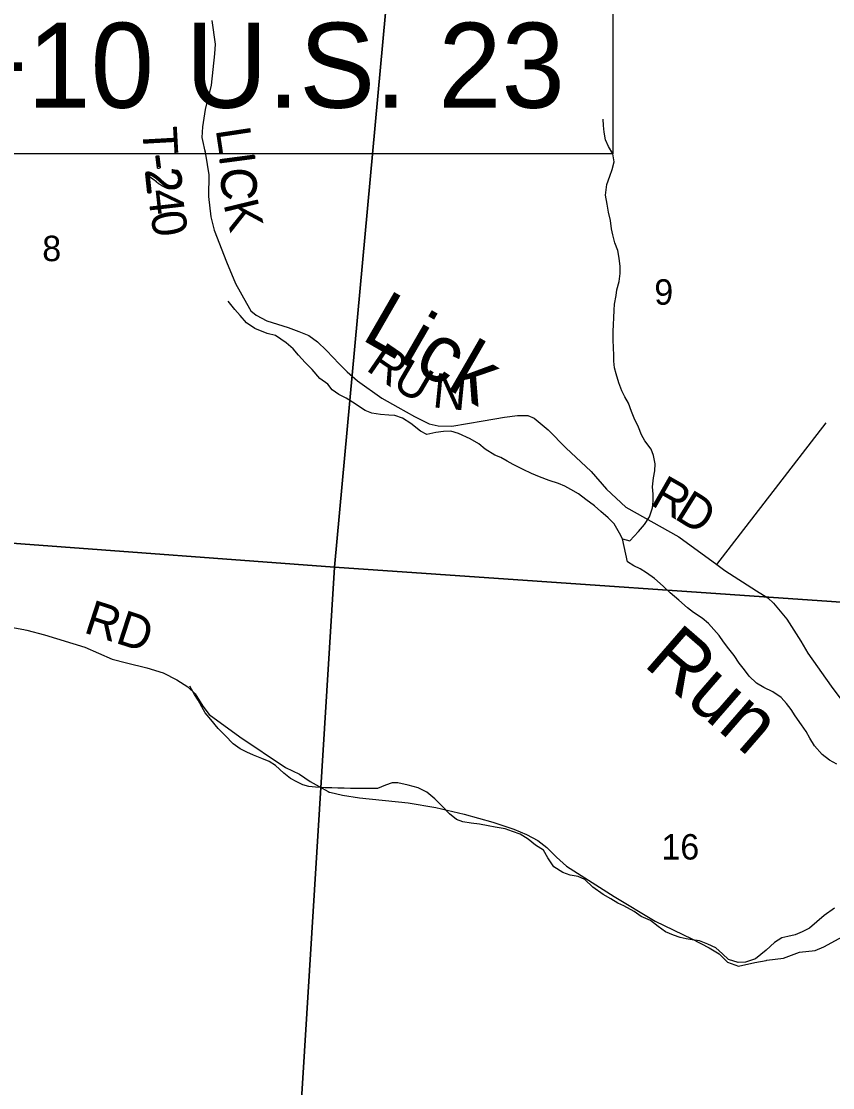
# Model space of a CAD drawing. Extents: x 0 to 34, y 0 to 22.
# Drawn here: x 6.981 to 8.316, y 15.475 to 17.231 of the extents above; entities that cross this region are included whole.
import ezdxf

# ---------------------------------------------------------------- set-up
doc = ezdxf.new("R2010")
doc.units = 0
for name, color, linetype in [('GM_X_Corporation', 7, 'Continuous'), ('GM_X_Minor_River', 7, 'Continuous'), ('GM_X_Minor_River_Text', 7, 'Continuous'), ('GM_X_Section_Text', 7, 'Continuous'), ('GM_X_Township_Road', 7, 'Continuous'), ('GM_X_Township_Road_Text', 7, 'Continuous'), ('SH_Data', 7, 'Continuous'), ('SH_Text', 7, 'Continuous')]:
    doc.layers.add(name, color=color, linetype=linetype)

msp = doc.modelspace()

# ---------------------------------------------------------------- linework, layer by layer
at = {"layer": 'GM_X_Corporation'}
for points in [[(6.5737, 17.4057), (7.5885, 17.3345), (7.4964, 16.3324), (6.463, 16.4089)], [(7.5885, 17.3345), (8.5882, 17.2585), (8.4813, 16.2644), (7.4964, 16.3324)], [(6.463, 16.4089), (7.4964, 16.3324), (7.434, 15.3319), (6.4021, 15.41)], [(7.4964, 16.3324), (8.4813, 16.2644), (8.4262, 15.2749), (7.434, 15.3319)]]:
    msp.add_lwpolyline(points, close=True, dxfattribs=at)
at = {"layer": 'GM_X_Minor_River'}
for p, q in [((7.9543, 17.0126), (7.9514, 17.0176)), ((7.9565, 16.9993), (7.9543, 17.0126)), ((7.9534, 16.9868), (7.9565, 16.9993)), ((7.9446, 16.9622), (7.9492, 16.9758)), ((7.9492, 16.9758), (7.9534, 16.9868)), ((7.9422, 16.9444), (7.9446, 16.9622)), ((7.9448, 16.9296), (7.9422, 16.9444))]:
    msp.add_line(p, q, dxfattribs=at)
for points in [[(7.9701, 16.3786), (7.9822, 16.3755), (7.9967, 16.391), (8.0066, 16.4023), (8.015, 16.4148), (8.0196, 16.43), (8.0208, 16.441), (8.0209, 16.4524), (8.0198, 16.4645), (8.0214, 16.4793), (8.0237, 16.491), (8.0241, 16.5024), (8.0215, 16.5161), (8.0174, 16.5267), (8.0069, 16.54), (8.0016, 16.5499), (7.9968, 16.5629), (7.9896, 16.5777), (7.9852, 16.5883), (7.9799, 16.602), (7.9743, 16.6126), (7.9694, 16.6225), (7.9642, 16.6354), (7.9597, 16.6506), (7.9571, 16.6605), (7.956, 16.6711), (7.9561, 16.6825), (7.9557, 16.6924), (7.9551, 16.7076), (7.9547, 16.7201), (7.9555, 16.7319), (7.956, 16.7425), (7.9564, 16.755), (7.9572, 16.7649), (7.9596, 16.7793), (7.9611, 16.7887), (7.9646, 16.8024), (7.9666, 16.8157), (7.9662, 16.8274), (7.9648, 16.8407), (7.9626, 16.8532), (7.9577, 16.8662), (7.9544, 16.8791), (7.9521, 16.8889), (7.9503, 16.903), (7.9474, 16.9163), (7.9448, 16.9296), (7.9422, 16.9444), (7.9446, 16.9622), (7.9492, 16.9758), (7.9534, 16.9868), (7.9565, 16.9993), (7.9543, 17.0126), (7.9475, 17.0244), (7.9423, 17.0358), (7.94, 17.048), (7.939, 17.059), (7.9386, 17.0696)], [(7.7904, 16.5014), (7.7806, 16.5067), (7.77, 16.5128), (7.7602, 16.5167), (7.7443, 16.5266), (7.7338, 16.535), (7.7194, 16.5434), (7.7001, 16.5522), (7.6876, 16.556), (7.6755, 16.5553), (7.663, 16.5538), (7.6482, 16.5508), (7.638, 16.5562), (7.6218, 16.5688), (7.6082, 16.5775), (7.5957, 16.5818), (7.5859, 16.5826), (7.5719, 16.5834), (7.5579, 16.5857), (7.5469, 16.5903), (7.5258, 16.6036), (7.5152, 16.6105), (7.5031, 16.6166), (7.4925, 16.6239), (7.485, 16.6334), (7.4722, 16.6429), (7.4593, 16.6574), (7.448, 16.6692), (7.4371, 16.6814), (7.4281, 16.6916), (7.4164, 16.7016), (7.399, 16.7134), (7.3854, 16.7168), (7.365, 16.7253), (7.3514, 16.7344), (7.3408, 16.7462), (7.3322, 16.7565), (7.3212, 16.7698)], [(8.3232, 16.0081), (8.3112, 16.0146), (8.2991, 16.0237), (8.2866, 16.0382), (8.2788, 16.0507), (8.2727, 16.0618), (8.2652, 16.0728), (8.2547, 16.0872), (8.2479, 16.0979), (8.2404, 16.1078), (8.2314, 16.1177), (8.2178, 16.1272), (8.203, 16.1341), (8.1909, 16.1414), (8.1789, 16.1528), (8.1713, 16.1634), (8.1623, 16.1741), (8.154, 16.1866), (8.1454, 16.1977), (8.1367, 16.2091), (8.1296, 16.2197), (8.1205, 16.2296), (8.1119, 16.2395), (8.1013, 16.2483), (8.0873, 16.2575), (8.0775, 16.2651), (8.0632, 16.278), (8.0489, 16.2899), (8.0375, 16.3009), (8.0228, 16.3135), (8.0096, 16.3226), (7.9994, 16.3295), (7.9888, 16.3345), (7.9783, 16.341), (7.9701, 16.3786), (7.9656, 16.3881), (7.9566, 16.4036), (7.9468, 16.4135), (7.9344, 16.4238), (7.9242, 16.4334), (7.9102, 16.4433), (7.8978, 16.4528), (7.8853, 16.4601), (7.8755, 16.4654), (7.8649, 16.47), (7.8494, 16.4746), (7.8335, 16.4811), (7.8203, 16.4865), (7.8067, 16.493), (7.7904, 16.5014)], [(7.2715, 16.1132), (7.2658, 16.1227), (7.2583, 16.1364)], [(8.3191, 15.7709), (8.3023, 15.7589), (8.2902, 15.7483), (8.2784, 15.7377), (8.2658, 15.7321), (8.2545, 15.7268), (8.2423, 15.7242), (8.2325, 15.7219), (8.2203, 15.7144), (8.2066, 15.7019), (8.1891, 15.6876), (8.1728, 15.6819), (8.1607, 15.6812), (8.1448, 15.6866), (8.135, 15.6957), (8.1237, 15.7053), (8.1108, 15.7118), (8.0972, 15.7168), (8.0851, 15.7187), (8.0749, 15.7202), (8.065, 15.7226), (8.0545, 15.7264), (8.0412, 15.7321), (8.0292, 15.7409), (8.0163, 15.7504), (8.0012, 15.7573), (7.9895, 15.7653), (7.9725, 15.7745), (7.9627, 15.7791), (7.951, 15.7863), (7.9385, 15.7932), (7.9215, 15.8054), (7.9083, 15.818), (7.8973, 15.823), (7.8841, 15.8249), (7.872, 15.8295), (7.8573, 15.8387), (7.8475, 15.8535), (7.8404, 15.8664), (7.8268, 15.8748), (7.8151, 15.8844), (7.8019, 15.8924), (7.7894, 15.8973), (7.7773, 15.9012), (7.7606, 15.9043), (7.7489, 15.9062), (7.7349, 15.9089), (7.7213, 15.9109), (7.7073, 15.9128), (7.697, 15.9167), (7.6857, 15.9262), (7.6729, 15.9395), (7.6612, 15.9509), (7.6484, 15.9616), (7.634, 15.9689), (7.6174, 15.9735), (7.6007, 15.9773), (7.5909, 15.9774), (7.5803, 15.9732), (7.567, 15.968), (7.5575, 15.9676), (7.5461, 15.9677), (7.5325, 15.9677), (7.5227, 15.9681), (7.5121, 15.9685), (7.5015, 15.9686), (7.4916, 15.969), (7.481, 15.969), (7.4651, 15.9702), (7.4541, 15.9714), (7.4439, 15.9741), (7.4341, 15.9787), (7.4239, 15.9844), (7.4129, 15.9932), (7.399, 16.0058), (7.3888, 16.0122), (7.3767, 16.0172), (7.3627, 16.0226), (7.3517, 16.0276), (7.3408, 16.0333), (7.3294, 16.0413), (7.3163, 16.055), (7.3046, 16.0664), (7.2925, 16.0813), (7.2831, 16.0923), (7.2778, 16.1022), (7.2715, 16.1132)]]:
    msp.add_lwpolyline(points, dxfattribs=at)
at = {"layer": 'GM_X_Township_Road'}
for p, q in [((7.2826, 17.0185), (7.284, 17.0121)), ((7.284, 17.0121), (7.2892, 16.9783)), ((7.2892, 16.9783), (7.2887, 16.9425)), ((8.1257, 16.3365), (8.3057, 16.5696))]:
    msp.add_line(p, q, dxfattribs=at)
for points in [[(7.2945, 17.2323), (7.2997, 17.1932), (7.2989, 17.1772), (7.2931, 17.1256), (7.2835, 17.0854), (7.2788, 17.0569), (7.278, 17.0394), (7.284, 17.0121), (7.2892, 16.9783), (7.2887, 16.9425), (7.2928, 16.9091), (7.298, 16.8871), (7.3184, 16.8346), (7.3334, 16.7993), (7.3515, 16.7665), (7.3583, 16.7544), (7.367, 16.7471), (7.3848, 16.7376), (7.42, 16.7269), (7.4374, 16.72), (7.4541, 16.7135), (7.4681, 16.7032), (7.4828, 16.6887), (7.504, 16.667), (7.5168, 16.6537), (7.5338, 16.6388), (7.5743, 16.6106), (7.6004, 16.5954), (7.628, 16.5801), (7.6519, 16.5679), (7.667, 16.5648), (7.6894, 16.5644), (7.7409, 16.5729), (7.7762, 16.5793), (7.7974, 16.5819), (7.8145, 16.5819), (7.8247, 16.5773), (7.8478, 16.5582), (7.8773, 16.5281), (7.9015, 16.5055), (7.9185, 16.4897), (7.9441, 16.4604), (7.9759, 16.431), (8.0629, 16.3822), (8.1257, 16.3365), (8.1389, 16.3269), (8.1911, 16.293), (8.2093, 16.2815), (8.2187, 16.2731), (8.2406, 16.2465), (8.264, 16.2103), (8.2753, 16.1906), (8.3138, 16.1365), (8.369, 16.0623)], [(6.9268, 16.2398), (6.9849, 16.2293)], [(6.9849, 16.2293), (6.9868, 16.229), (6.9897, 16.2284), (7.0188, 16.2209), (7.0854, 16.2004), (7.1299, 16.1805), (7.1537, 16.1745), (7.1874, 16.1662), (7.2142, 16.1583), (7.2369, 16.1466), (7.2545, 16.135), (7.2669, 16.1235), (7.2796, 16.1036), (7.2896, 16.0899), (7.3404, 16.0528), (7.4153, 16.0026), (7.4383, 15.9917), (7.456, 15.9794), (7.4858, 15.963)], [(7.4858, 15.963), (7.4875, 15.962), (7.4884, 15.9616), (7.5096, 15.9568), (7.5372, 15.9526), (7.6176, 15.9441), (7.663, 15.9368), (7.7099, 15.9256), (7.7568, 15.9125), (7.7916, 15.9008), (7.812, 15.8922), (7.8308, 15.8821), (7.8459, 15.8709), (7.8616, 15.8548), (7.8781, 15.8402), (7.9568, 15.7899), (8.0242, 15.7497), (8.0842, 15.7201), (8.1132, 15.7057), (8.1294, 15.6957), (8.1429, 15.6819), (8.1614, 15.6756), (8.1884, 15.6813), (8.2067, 15.6849), (8.2077, 15.685)], [(8.2077, 15.685), (8.2352, 15.6888), (8.2619, 15.6983), (8.2877, 15.7014), (8.3018, 15.7073), (8.3332, 15.7244), (8.3511, 15.7333), (8.4189, 15.7512), (8.4387, 15.754), (8.4504, 15.7542)]]:
    msp.add_lwpolyline(points, dxfattribs=at)
at = {"layer": 'GM_X_Township_Road_Text'}
for p, q in [((7.3088, 17.0029), (7.3631, 17.0101)), ((7.2047, 16.9897), (7.2028, 17.0079)), ((7.2072, 17.0084), (7.2091, 16.9901)), ((7.3638, 17.0048), (7.3095, 16.9976)), ((7.1891, 16.9492), (7.1858, 16.9795)), ((7.1913, 16.9809), (7.2048, 16.9707)), ((7.2071, 16.9887), (7.2071, 16.9887)), ((7.1917, 16.9478), (7.1917, 16.9478)), ((7.319, 16.9443), (7.319, 16.9443))]:
    msp.add_line(p, q, dxfattribs=at)
msp.add_lwpolyline([(7.2029, 16.9663), (7.191, 16.9754), (7.1938, 16.9497)], dxfattribs=at)
for points in [[(7.3631, 17.0101), (7.3634, 17.0101), (7.3636, 17.01)], [(7.3636, 17.01), (7.3639, 17.0098), (7.364, 17.0095)], [(7.2028, 17.0079), (7.2027, 17.0085), (7.2032, 17.0089)], [(7.2032, 17.0089), (7.2036, 17.0093), (7.2048, 17.0094)], [(7.2048, 17.0094), (7.2061, 17.0096), (7.2066, 17.0093)], [(7.2066, 17.0093), (7.2071, 17.0089), (7.2072, 17.0084)], [(7.3079, 17.0013), (7.308, 17.0019), (7.308, 17.0022)], [(7.308, 17.0001), (7.3079, 17.0008), (7.3079, 17.0013)], [(7.308, 17.0022), (7.3081, 17.0025), (7.3083, 17.0027)], [(7.3083, 16.9988), (7.3081, 16.9993), (7.308, 17.0001)], [(7.3083, 17.0027), (7.3085, 17.0028), (7.3088, 17.0029)], [(7.3086, 16.998), (7.3084, 16.9983), (7.3083, 16.9988)], [(7.309, 16.9976), (7.3088, 16.9977), (7.3086, 16.998)], [(7.3095, 16.9976), (7.3092, 16.9975), (7.309, 16.9976)], [(7.3643, 17.005), (7.3641, 17.0048), (7.3638, 17.0048)], [(7.364, 17.0095), (7.3642, 17.0092), (7.3644, 17.0087)], [(7.3646, 17.0054), (7.3645, 17.0051), (7.3643, 17.005)], [(7.3644, 17.0087), (7.3645, 17.0083), (7.3646, 17.0076)], [(7.3646, 17.0076), (7.3647, 17.0068), (7.3647, 17.0063)], [(7.3647, 17.0063), (7.3647, 17.0058), (7.3646, 17.0054)], [(7.1858, 16.9803), (7.1859, 16.9806), (7.1862, 16.9809)], [(7.1858, 16.9795), (7.1857, 16.9799), (7.1858, 16.9803)], [(7.1862, 16.9809), (7.1864, 16.9812), (7.1869, 16.9814)], [(7.1869, 16.9814), (7.1874, 16.9816), (7.188, 16.9817)], [(7.188, 16.9817), (7.1886, 16.9817), (7.189, 16.9817)], [(7.189, 16.9817), (7.1894, 16.9817), (7.1898, 16.9816)], [(7.1898, 16.9816), (7.1902, 16.9816), (7.1905, 16.9814)], [(7.1905, 16.9814), (7.1909, 16.9812), (7.1913, 16.9809)], [(7.2053, 16.9888), (7.2048, 16.9891), (7.2047, 16.9897)], [(7.2071, 16.9887), (7.2058, 16.9885), (7.2053, 16.9888)], [(7.2081, 16.9888), (7.2077, 16.9887), (7.2071, 16.9887)], [(7.2087, 16.9892), (7.2085, 16.989), (7.2081, 16.9888)], [(7.209, 16.9896), (7.209, 16.9894), (7.2087, 16.9892)], [(7.2091, 16.9901), (7.2091, 16.9899), (7.209, 16.9896)], [(7.2332, 16.9844), (7.2332, 16.9847), (7.2333, 16.9849)], [(7.2342, 16.9829), (7.2333, 16.9839), (7.2332, 16.9844)], [(7.2333, 16.9849), (7.2334, 16.9851), (7.2337, 16.9853)], [(7.2337, 16.9853), (7.234, 16.9855), (7.2344, 16.9856)], [(7.2362, 16.9804), (7.2351, 16.9819), (7.2342, 16.9829)], [(7.2344, 16.9856), (7.2348, 16.9857), (7.2354, 16.9858)], [(7.2354, 16.9858), (7.2359, 16.9858), (7.2363, 16.9858)], [(7.2383, 16.9767), (7.2373, 16.9788), (7.2362, 16.9804)], [(7.2363, 16.9858), (7.2366, 16.9858), (7.2369, 16.9858)], [(7.2369, 16.9858), (7.2372, 16.9857), (7.2375, 16.9856)], [(7.2375, 16.9856), (7.2377, 16.9855), (7.2382, 16.985)], [(7.2382, 16.985), (7.2387, 16.9846), (7.2396, 16.9834)], [(7.2396, 16.9719), (7.2393, 16.9747), (7.2383, 16.9767)], [(7.2396, 16.9834), (7.2405, 16.9823), (7.2414, 16.9806)], [(7.2414, 16.9806), (7.2424, 16.9789), (7.2432, 16.9767)], [(7.2432, 16.9767), (7.244, 16.9745), (7.2442, 16.9722)], [(7.3117, 16.971), (7.3134, 16.9753), (7.3169, 16.9785)], [(7.3169, 16.9785), (7.3204, 16.9817), (7.3255, 16.9835)], [(7.3281, 16.9782), (7.3237, 16.9768), (7.3208, 16.9744)], [(7.3255, 16.9835), (7.3307, 16.9853), (7.3375, 16.9855)], [(7.338, 16.9798), (7.3324, 16.9796), (7.3281, 16.9782)], [(7.3375, 16.9855), (7.3444, 16.9857), (7.3499, 16.9842)], [(7.3485, 16.9788), (7.3439, 16.98), (7.338, 16.9798)], [(7.3563, 16.9753), (7.3531, 16.9776), (7.3485, 16.9788)], [(7.3499, 16.9842), (7.3555, 16.9826), (7.3594, 16.9796)], [(7.3612, 16.9698), (7.3595, 16.9731), (7.3563, 16.9753)], [(7.3594, 16.9796), (7.3633, 16.9765), (7.3655, 16.9722)], [(7.2125, 16.9597), (7.2084, 16.9621), (7.2029, 16.9663)], [(7.2048, 16.9707), (7.2097, 16.9669), (7.2136, 16.9648)], [(7.22, 16.9561), (7.2166, 16.9573), (7.2125, 16.9597)], [(7.2136, 16.9648), (7.2174, 16.9626), (7.2204, 16.9616)], [(7.2204, 16.9616), (7.2235, 16.9606), (7.2259, 16.9604)], [(7.2259, 16.9604), (7.2283, 16.9602), (7.2303, 16.9605)], [(7.2303, 16.9605), (7.2324, 16.9607), (7.2342, 16.9616)], [(7.2342, 16.9616), (7.2361, 16.9625), (7.2373, 16.9639)], [(7.2412, 16.9599), (7.2394, 16.9578), (7.2369, 16.9565)], [(7.2373, 16.9639), (7.2386, 16.9654), (7.2392, 16.9674)], [(7.2392, 16.9674), (7.2399, 16.9694), (7.2396, 16.9719)], [(7.2438, 16.9652), (7.243, 16.9621), (7.2412, 16.9599)], [(7.2442, 16.9722), (7.2447, 16.9682), (7.2438, 16.9652)], [(7.3101, 16.9612), (7.31, 16.9666), (7.3117, 16.971)], [(7.311, 16.9552), (7.3103, 16.9579), (7.3101, 16.9612)], [(7.3164, 16.9685), (7.315, 16.9651), (7.3151, 16.9608)], [(7.3151, 16.9608), (7.3152, 16.9572), (7.3162, 16.9546)], [(7.3208, 16.9744), (7.3179, 16.972), (7.3164, 16.9685)], [(7.363, 16.9625), (7.3629, 16.9665), (7.3612, 16.9698)], [(7.3623, 16.9563), (7.3631, 16.9589), (7.363, 16.9625)], [(7.3655, 16.9722), (7.3677, 16.9678), (7.3679, 16.9624)], [(7.3675, 16.9575), (7.3671, 16.9551), (7.3665, 16.9531)], [(7.3679, 16.9624), (7.3679, 16.9599), (7.3675, 16.9575)], [(7.1894, 16.9485), (7.1891, 16.9488), (7.1891, 16.9492)], [(7.1899, 16.9481), (7.1896, 16.9482), (7.1894, 16.9485)], [(7.1907, 16.9478), (7.1902, 16.9479), (7.1899, 16.9481)], [(7.1917, 16.9478), (7.1912, 16.9478), (7.1907, 16.9478)], [(7.1926, 16.948), (7.1922, 16.9479), (7.1917, 16.9478)], [(7.1933, 16.9485), (7.1931, 16.9482), (7.1926, 16.948)], [(7.1937, 16.949), (7.1936, 16.9487), (7.1933, 16.9485)], [(7.1938, 16.9497), (7.1939, 16.9493), (7.1937, 16.949)], [(7.226, 16.9548), (7.2233, 16.955), (7.22, 16.9561)], [(7.2314, 16.955), (7.2287, 16.9547), (7.226, 16.9548)], [(7.2369, 16.9565), (7.2343, 16.9553), (7.2314, 16.955)], [(7.3127, 16.9504), (7.3118, 16.9525), (7.311, 16.9552)], [(7.3147, 16.9469), (7.3137, 16.9483), (7.3127, 16.9504)], [(7.3161, 16.9452), (7.3157, 16.9456), (7.3147, 16.9469)], [(7.3168, 16.9446), (7.3166, 16.9448), (7.3161, 16.9452)], [(7.3162, 16.9546), (7.3172, 16.952), (7.3184, 16.9501)], [(7.3174, 16.9444), (7.3171, 16.9445), (7.3168, 16.9446)], [(7.3181, 16.9443), (7.3177, 16.9443), (7.3174, 16.9444)], [(7.319, 16.9443), (7.3185, 16.9442), (7.3181, 16.9443)], [(7.3184, 16.9501), (7.3195, 16.9483), (7.3205, 16.9471)], [(7.3202, 16.9444), (7.3197, 16.9443), (7.319, 16.9443)], [(7.3209, 16.9446), (7.3207, 16.9445), (7.3202, 16.9444)], [(7.3205, 16.9471), (7.3214, 16.946), (7.3214, 16.9453)], [(7.3213, 16.9449), (7.3212, 16.9447), (7.3209, 16.9446)], [(7.3214, 16.9453), (7.3214, 16.945), (7.3213, 16.9449)], [(7.3578, 16.947), (7.3577, 16.9476), (7.3586, 16.9488)], [(7.358, 16.9465), (7.3578, 16.9467), (7.3578, 16.947)], [(7.3585, 16.9461), (7.3581, 16.9463), (7.358, 16.9465)], [(7.3593, 16.946), (7.3588, 16.946), (7.3585, 16.9461)], [(7.3586, 16.9488), (7.3595, 16.9499), (7.3605, 16.9518)], [(7.3603, 16.9459), (7.3597, 16.9459), (7.3593, 16.946)], [(7.3613, 16.946), (7.3609, 16.9459), (7.3603, 16.9459)], [(7.3605, 16.9518), (7.3615, 16.9536), (7.3623, 16.9563)], [(7.362, 16.9462), (7.3617, 16.9461), (7.3613, 16.946)], [(7.3626, 16.9464), (7.3623, 16.9463), (7.362, 16.9462)], [(7.3634, 16.9472), (7.3628, 16.9466), (7.3626, 16.9464)], [(7.3649, 16.9494), (7.364, 16.9478), (7.3634, 16.9472)], [(7.3665, 16.9531), (7.3658, 16.9511), (7.3649, 16.9494)]]:
    msp.add_open_spline(points, degree=2, dxfattribs=at)
at = {"layer": 'SH_Data'}
for p, q in [((7.9543, 17.4995), (7.9543, 17.0126)), ((7.9543, 17.0126), (6.0621, 17.0126))]:
    msp.add_line(p, q, dxfattribs=at)

# ---------------------------------------------------------------- texts
at = {"layer": 'GM_X_Minor_River_Text'}
for s, height, rotation, p in [('Lick', 0.09469, 330.0025, (7.5381, 16.7083)), ('Run', 0.0947, 318.9985, (8.0027, 16.1715))]:
    msp.add_text(s, height=height, rotation=rotation, dxfattribs=at).set_placement(p)
at = {"layer": 'GM_X_Section_Text'}
for s, height, p in [('8', 0.0419, (7.0151, 16.8359)), ('9', 0.0419, (8.0226, 16.7642)), ('16', 0.04186, (8.0343, 15.8509))]:
    msp.add_text(s, height=height, rotation=0, dxfattribs=at).set_placement(p)
at = {"layer": 'GM_X_Township_Road_Text'}
for s, height, rotation, p in [('T', 0.0568, 273.2331, (7.1798, 17.0558)), ('L', 0.0568, 278.5865, (7.3005, 17.0527)), ('-', 0.0568, 276.0821, (7.1825, 17.0103)), ('I', 0.0568, 277.5549, (7.3068, 17.0109)), ('2', 0.0568, 276.2334, (7.185, 16.987)), ('C', 0.0568, 271.9323, (7.3098, 16.9893)), ('4', 0.0568, 276.4095, (7.1888, 16.952)), ('K', 0.0568, 283.6679, (7.3131, 16.9301)), ('0', 0.0568, 278.7858, (7.193, 16.9147)), ('R', 0.0568, 325.4742, (7.5462, 16.6575)), ('U', 0.0568, 329.8416, (7.5886, 16.6286)), ('N', 0.0568, 354.3024, (7.6564, 16.5955)), ('R', 0.0568, 330.2217, (8.0136, 16.4361)), ('D', 0.0568, 328.0954, (8.0537, 16.4132)), ('RD', 0.05682, 342.0373, (7.0814, 16.2251))]:
    msp.add_text(s, height=height, rotation=rotation, dxfattribs=at).set_placement(p)
at = {"layer": 'SH_Text'}
msp.add_text('STA. 814+10 U.S. 23', height=0.14, dxfattribs=at).set_placement((6.1009, 17.0884))

doc.saveas('drawing.dxf')
